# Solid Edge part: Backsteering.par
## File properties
Author: KULL
Template: Iso Metric Part.par
Last saved by: KULL
Revision: 2
Application: Solid Edge
Accuracy: 0,990
Face Style: Model Default
Fill Style: Normal
Coef. of Thermal Exp: 0.0
Thermal Conductivity: 0.0
Specific Heat: 0.0
Modulus of Elasticity: 0.0
Poisson's Ratio: 0.0
Yield Stress: 0.0
Ultimate Stress: 0.0
Elongation: 0.0
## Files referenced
..\..\Rover_ASM.asm
D:\Solid edge leong\Solid edge Sync practice\ROVER_Heiko_Kull_EKSAM\Raam\Chassy_1.par
D:\Solid edge leong\Solid edge Sync practice\ROVER_Heiko_Kull_EKSAM\Roolimise_jupid\frontsteering_1.par
D:\Solid edge leong\Solid edge Sync practice\ROVER_Heiko_Kull_EKSAM\Vedrustus\Tagumine66tshoob_1.par
QD:\Solid edge leong\Solid edge Sync practice\ROVER_Heiko_Kull_EKSAM\Rover_ASM.asm
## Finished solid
Body 1: sheet body, 3 faces, 10 edges, 8 vertices.
  Faces by surface: plane 3
  Edges by curve: line 8, circle 2
Body 2: solid body, 7 faces, 4 edges, 0 vertices, 3 separate solids.
  Faces by surface: plane 3, cylinder 2, sphere 2
  Edges by curve: circle 4
Body 3: sheet body, 1 face, 1 edge, 0 vertices.
  Faces by surface: sphere 1
  Edges by curve: circle 1
Body 4: sheet body, 1 face, 1 edge, 0 vertices.
  Faces by surface: sphere 1
  Edges by curve: circle 1
Bounding box of the edges (mm; curved faces can reach further): 350.642 x 27.000 x 54.000, from (-348.46, 105.6693, 1.2645) to (2.1818, 132.6693, 55.2645).
Cylindrical faces by radius (mm): R4 x1, R6 x1
Spherical faces by radius (mm): R4 x4
Planar faces by outward normal: +y 2, -y 1
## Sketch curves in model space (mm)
line (-342.46, 109.6693, 51.2645) -> (-342.46, 109.6693, 5.2645)
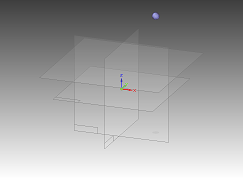
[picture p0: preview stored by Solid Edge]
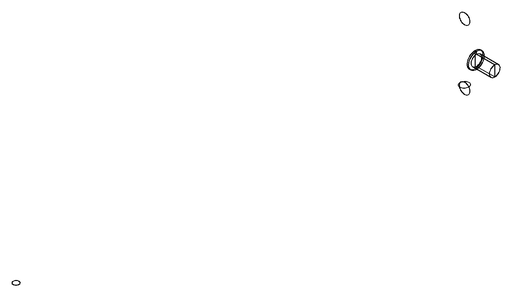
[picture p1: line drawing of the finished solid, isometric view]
